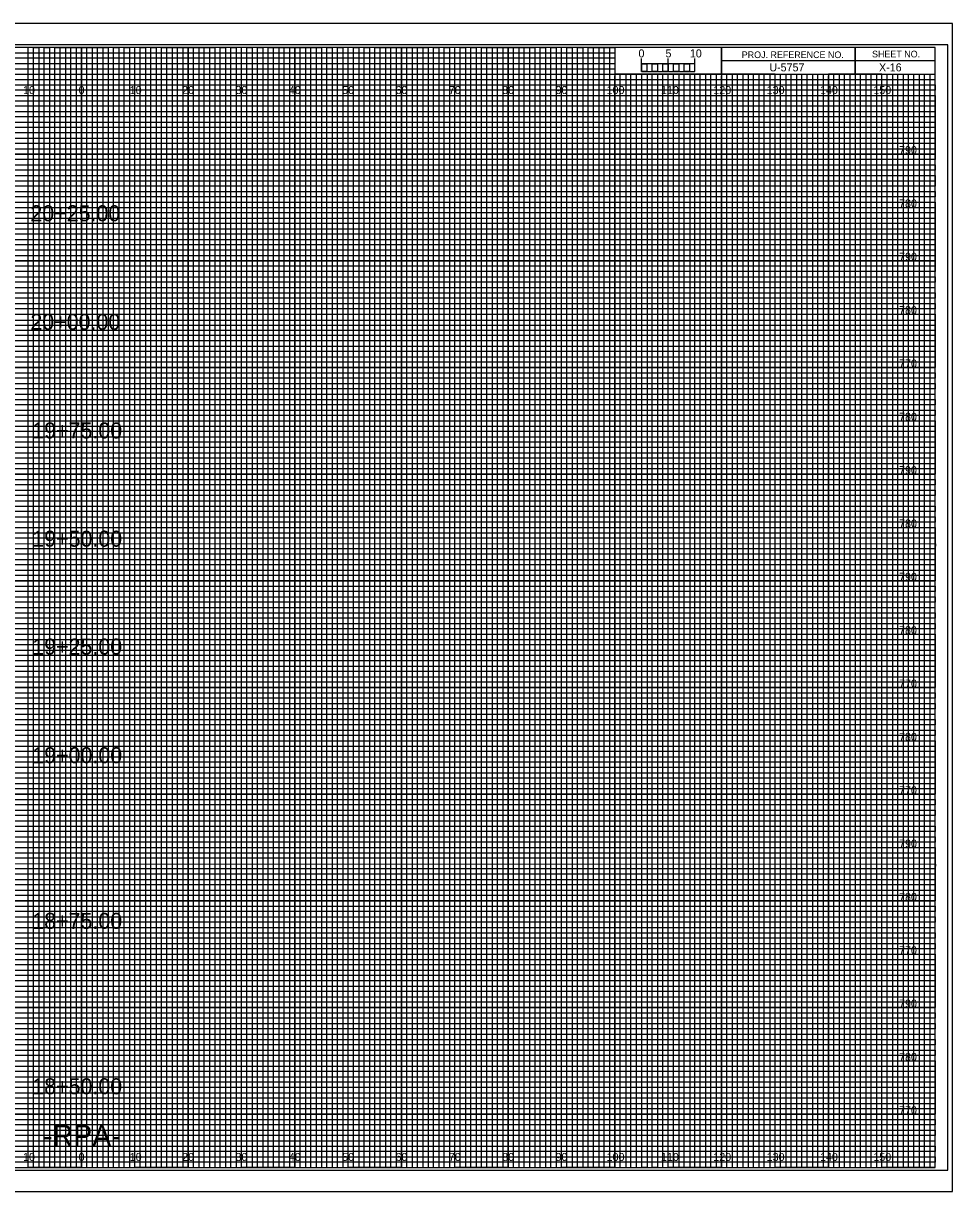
# Model space of a CAD drawing. Extents: x -13 to 323, y -5 to 215.
# Drawn here: x 149.1 to 323.3, y -4.5 to 214.5 of the extents above; entities that cross this region are included whole.
import ezdxf

# ---------------------------------------------------------------- set-up
doc = ezdxf.new("R2010")
doc.units = 0
for name, color, linetype in [('Exist Cross Section Cell', 7, 'Continuous'), ('Exist XS Center Line Elevation Label', 7, 'Continuous'), ('Exist XS Ground Line', 7, 'Continuous'), ('Prop CMT Pvmt Course 2', 7, 'Continuous'), ('Prop XS Alignment Label', 7, 'Continuous'), ('Prop XS Bar Scale Labels', 7, 'Continuous'), ('Prop XS DDE', 7, 'Continuous'), ('Prop XS DDE Elevations', 7, 'Continuous'), ('Prop XS Elevation Labels', 7, 'Continuous'), ('Prop XS Offset Labels', 7, 'Continuous'), ('Prop XS Project Number', 7, 'Continuous'), ('Prop XS Sheet Number', 7, 'Continuous'), ('Prop XS Side Slope Text', 7, 'Continuous'), ('Prop XS Station Labels', 7, 'Continuous'), ('Sheet Cutting Line CELL', 7, 'Continuous'), ('Sheet DOT Grid CELL', 7, 'Continuous'), ('Sheet Plot Border Outside CELL', 7, 'Continuous')]:
    doc.layers.add(name, color=color, linetype=linetype)

msp = doc.modelspace()

# ---------------------------------------------------------------- linework, layer by layer
at = {"layer": 'Exist Cross Section Cell'}
for p, q in [((150, 210), (140, 210)), ((150, 0), (150, 210)), ((170, 210), (160, 210)), ((160, 210), (160, 0)), ((170, 0), (170, 210)), ((190, 210), (180, 210)), ((180, 210), (180, 0)), ((190, 0), (190, 210)), ((210, 210), (200, 210)), ((200, 210), (200, 0)), ((210, 0), (210, 210)), ((230, 210), (220, 210)), ((220, 210), (220, 0)), ((230, 0), (230, 210)), ((250, 210), (240, 210)), ((240, 210), (240, 0)), ((250, 0), (250, 210)), ((260, 210), (260, 0)), ((270, 0), (270, 205)), ((290, 205), (280, 205)), ((280, 205), (280, 0)), ((290, 0), (290, 205)), ((310, 205), (300, 205)), ((300, 205), (300, 0)), ((310, 0), (310, 205)), ((160, 0), (150, 0)), ((180, 0), (170, 0)), ((200, 0), (190, 0)), ((220, 0), (210, 0)), ((240, 0), (230, 0)), ((260, 0), (250, 0)), ((280, 0), (270, 0)), ((300, 0), (290, 0)), ((320, 0), (310, 0)), ((320, 0), (320, 0))]:
    msp.add_line(p, q, dxfattribs=at)
for points in [[(0, 200), (320, 200), (320, 190), (0, 190)], [(0, 180), (320, 180), (320, 170), (0, 170)], [(0, 160), (320, 160), (320, 150), (0, 150)], [(0, 140), (320, 140), (320, 130), (0, 130)], [(0, 120), (320, 120), (320, 110), (0, 110)], [(0, 100), (320, 100), (320, 90), (0, 90)], [(0, 80), (320, 80), (320, 70), (0, 70)], [(0, 60), (320, 60), (320, 50), (0, 50)], [(0, 40), (320, 40), (320, 30), (0, 30)], [(0, 20), (320, 20), (320, 10), (0, 10)]]:
    msp.add_lwpolyline(points, dxfattribs=at)
at = {"layer": 'Exist XS Center Line Elevation Label'}
for p, q in [((0, 209), (260, 209)), ((260, 209), (260, 207.98)), ((260, 207.98), (0, 207.98)), ((0, 207), (260, 207)), ((260, 205.89), (0, 205.89)), ((260, 207), (260, 205.89)), ((0, 204), (320, 204))]:
    msp.add_line(p, q, dxfattribs=at)
for points in [[(0, 203), (270, 203), (320, 203), (320, 202), (0, 202)], [(0, 201), (320, 201), (320, 199), (0, 199)], [(0, 198), (320, 198), (320, 197), (0, 196.98)], [(0, 196), (320, 196), (320, 194), (0, 194)], [(0, 193), (320, 193), (320, 192), (0, 192)], [(0, 191), (320, 191), (320, 189), (0, 189)], [(0, 188), (320, 188), (320, 187), (0, 187)], [(0, 186), (320, 186), (320, 184), (0, 184)], [(0, 183), (320, 183), (320, 182), (0, 182)], [(0, 181), (320, 181), (320, 179), (0, 179)], [(0, 178), (320, 178), (320, 177), (0, 177)], [(0, 176), (320, 176), (320, 173.95), (320, 173), (320, 172), (0, 172)], [(0, 174), (320, 174), (320, 173), (0, 173)], [(0, 171), (320, 171), (320, 169), (0, 169.03)], [(0, 169.03), (320, 169), (320, 168), (0, 168)], [(0, 167), (320, 167), (320, 166), (0, 166)], [(0, 164), (320, 164), (320, 163), (0, 163)], [(0, 162), (320, 162), (320, 161), (0, 161)], [(-0.07, 158.89), (320, 158.89), (320, 157.88), (-0.07, 157.88)], [(0, 157), (320, 157), (320, 156), (0, 156)], [(0, 154), (320, 154), (320, 153), (0, 153)], [(0, 152), (320, 152), (320, 151), (0, 151)], [(0, 149), (320, 149), (320, 148), (0, 148)], [(0, 147), (320, 147), (320, 146), (0, 146)], [(0, 144), (320, 144), (320, 143), (0, 143)], [(0, 142), (320, 142), (320, 141), (0, 141)], [(0, 139), (320, 139), (319.99, 137.98), (0, 138)], [(0, 137), (320, 137), (320, 136), (0, 136)], [(0, 134), (320, 134), (320, 133), (0, 133)], [(0, 132), (320, 132), (320, 131), (0, 131)], [(0, 129), (320, 129), (320, 128), (0, 128)], [(0, 127), (320, 127), (320, 126), (0, 126)], [(0, 124), (320, 124), (320, 123), (0, 123)], [(0, 122), (320, 122), (320, 121), (0, 121)], [(0, 119), (320, 119), (320, 118), (0, 118)], [(0, 116.99), (320.07, 116.91), (320, 116), (0, 116)], [(0, 114), (320, 114), (320, 113), (0, 113)], [(0, 112), (320, 112), (320, 111), (0, 111)], [(0, 109), (320, 109), (320, 108), (0, 108)], [(0, 107), (320, 107), (320, 106), (0, 106)], [(0, 104), (320, 104), (320, 103), (0, 103)], [(0, 102), (320, 102), (320, 101), (0, 101)], [(0, 99), (320, 99), (320, 98), (0, 98)], [(0, 97), (320, 97), (320, 96), (0, 96)], [(0, 94), (320, 94), (320, 93), (0, 93)], [(0, 92), (320, 92), (320, 91), (0, 91)], [(0, 89), (320, 89), (320, 88), (0, 88)], [(0, 87), (320, 87), (320, 86), (0, 86)], [(0, 84), (320, 84), (320, 83), (0, 83)], [(0, 82), (320, 82), (320, 81), (0, 81)], [(0, 79), (320, 79), (319.99, 77.98), (0, 78)], [(0, 77), (320, 77), (320, 76), (0, 76)], [(0, 74), (320, 74), (320, 73), (0, 73)], [(0, 72), (320, 72), (320, 71), (0, 71)], [(0, 69), (320, 69), (320, 68), (0, 68)], [(0, 67), (320, 67), (320, 66), (0, 66)], [(0, 64), (320, 64), (320, 63), (0, 63)], [(0, 62), (320, 62), (320, 61), (0, 61)], [(0, 59), (320, 59), (320, 58), (0, 58)], [(0, 56.99), (320.07, 56.91), (320, 56), (0, 56)], [(0, 54), (320, 54), (320, 53), (0, 53)], [(0, 52), (320, 52), (320, 51), (0, 51)], [(0, 49), (320, 49), (320, 48), (0, 48)], [(0, 47), (320, 47), (320, 46), (0, 46)], [(0, 44), (320, 44), (320, 43), (0, 43)], [(0, 42), (320, 42), (320, 41), (0, 41)], [(0, 39), (320, 39), (320, 38), (0, 38)], [(0, 37), (320, 37), (320, 36), (0, 36)], [(0, 34), (320, 34), (320, 33), (0, 33)], [(0, 32), (320, 32), (320, 31), (0, 31)], [(0, 29), (320, 29), (320, 28), (0, 28)], [(0, 27), (320, 27), (320, 26), (0, 26)], [(0, 24), (320, 24), (320, 23), (0, 23)], [(0, 22), (320, 22), (320, 21), (0, 21)], [(0, 19), (320, 19), (320, 18), (0, 18)], [(0, 17), (320, 17), (320, 16), (0, 16)], [(0, 14), (320, 14), (320, 13), (0, 13)], [(0, 12), (320, 12), (320, 11), (0, 11)], [(0, 9), (320, 9), (320, 8), (0, 8)], [(0, 7), (320, 7), (320, 6), (0, 6)], [(0, 4), (320, 4), (320, 3), (0, 3)], [(0, 2), (320, 2), (320, 1), (0, 1)]]:
    msp.add_lwpolyline(points, dxfattribs=at)
at = {"layer": 'Exist XS Ground Line'}
for points in [[(145, 0), (155, 0), (155, 210), (165, 210), (165, 0), (175, 0), (175, 210), (185, 210), (185, 0), (195, 0), (195, 210), (205, 210), (205, 0), (215, 0), (215, 210), (225, 210), (225, 0), (235, 0), (235, 210), (245, 210), (245, 0), (255, 0), (255, 210), (259.93, 210), (260, 210), (260, 205), (264.99, 205), (264.99, 0), (275, 0), (275, 205), (285, 205), (285, 0), (295, 0), (295, 205), (305, 205), (305, 0), (315, 0), (315, 205)], [(0, 205), (275, 205)], [(0, 185), (320, 185), (320, 195), (0, 195)], [(0, 165), (320, 165), (320, 175), (0, 175)], [(0, 145), (320, 145), (320, 155), (0, 155)], [(0, 125), (320, 125), (320, 135), (0, 135)], [(0, 105), (320, 105), (320, 115), (0, 115)], [(0, 85), (320, 85), (320, 95), (0, 95)], [(0, 65), (320, 65), (320, 75), (0, 75)], [(0, 45), (320, 45), (320, 55), (0, 55)], [(0, 25), (320, 25), (320, 35), (0, 35)], [(0, 5), (320, 5), (320, 15), (0, 15)]]:
    msp.add_lwpolyline(points, dxfattribs=at)
at = {"layer": 'Prop CMT Pvmt Course 2'}
msp.add_lwpolyline([(-10.8, -0.5), (322.4, -0.5), (322.4, 210.5), (-10.8, 210.5)], close=True, dxfattribs=at)
at = {"layer": 'Prop XS DDE'}
for p, q in [((305, 210), (305, 205)), ((305, 205), (305, 210)), ((280, 207.5), (280, 205)), ((320, 207.49), (280, 207.49)), ((280, 205), (320, 205))]:
    msp.add_line(p, q, dxfattribs=at)
for points in [[(320, 210), (0, 210), (0, 0), (320, 0)], [(280, 210), (260, 210), (260, 205.03), (280, 205.03)], [(320, 210), (280, 210), (280, 205), (320, 205)]]:
    msp.add_lwpolyline(points, close=True, dxfattribs=at)
at = {"layer": 'Prop XS DDE Elevations'}
for p, q in [((267, 205), (266.01, 205)), ((266.01, 205), (266.01, 0)), ((267, 0), (267, 205)), ((269, 205), (268, 205)), ((268, 205), (268, 0)), ((269, 0), (269, 205)), ((266.01, 0), (265, 0)), ((268, 0), (267, 0))]:
    msp.add_line(p, q, dxfattribs=at)
for points in [[(150, 0), (151, 0), (151, 210), (152, 210), (152, 0)], [(152, 0), (153, 0), (153, 210), (154, 210), (154, 0)], [(155, 0), (156, 0), (156, 210), (157, 210), (157, 0)], [(157, 0), (158, 0), (158, 210), (159, 210), (159, 0)], [(160, 0), (161, 0), (161, 210), (162, 210), (162, 0)], [(162, 0), (163, 0), (163, 210), (164, 210), (164, 0)], [(165, 0), (166, 0), (166, 210), (167, 210), (167, 0)], [(167, 0), (168, 0), (168, 210), (169, 210), (169, 0)], [(170, 0), (171, 0), (171, 210), (172, 210), (172, 0)], [(172, 0), (173, 0), (173, 210), (174, 210), (174, 0)], [(175, 0), (176, 0), (176, 210), (177, 210), (177, 0)], [(177, 0), (178, 0), (178, 210), (179, 210), (179, 0)], [(180, 0), (181, 0), (181, 210), (182, 210), (182, 0)], [(182, 0), (183, 0), (183, 210), (184, 210), (184, 0)], [(185, 0), (186, 0), (186, 210), (187, 210), (187, 0)], [(187, 0), (188, 0), (188, 210), (189, 210), (189, 0)], [(190, 0), (191, 0), (191, 210), (192, 210), (192, 0)], [(192, 0), (193, 0), (193, 210), (194, 210), (194, 0)], [(195, 0), (196, 0), (196, 210), (197, 210), (197, 0)], [(197, 0), (198, 0), (198, 210), (199, 210), (199, 0)], [(200, 0), (201, 0), (201, 210), (202, 210), (202, 0)], [(202, 0), (203, 0), (203, 210), (204, 210), (204, 0)], [(205, 0), (206, 0), (206, 210), (207, 210), (207, 0)], [(207, 0), (208, 0), (208, 210), (209, 210), (209, 0)], [(210, 0), (211, 0), (211, 210), (212, 210), (212, 0)], [(212, 0), (213, 0), (213, 210), (214, 210), (214, 0)], [(215, 0), (216, 0), (216, 210), (217, 210), (217, 0)], [(217, 0), (218, 0), (218, 210), (219, 210), (219, 0)], [(220, 0), (221, 0), (221, 210), (222, 210), (222, 0)], [(222, 0), (223, 0), (223, 210), (224, 210), (224, 0)], [(225, 0), (226, 0), (226, 210), (227, 210), (227, 0)], [(227, 0), (228, 0), (228, 210), (229, 210), (229, 0)], [(230, 0), (231, 0), (231, 210), (232, 210), (232, 0)], [(232, 0), (233, 0), (233, 210), (234, 210), (234, 0)], [(235, 0), (236, 0), (236, 210), (237, 210), (237, 0)], [(237, 0), (238, 0), (238, 210), (239, 210), (239, 0)], [(240, 0), (241, 0), (241, 210), (242, 210), (242, 0)], [(242, 0), (243, 0), (243, 210), (244, 210), (244, 0)], [(245, 0), (246, 0), (246, 210), (247, 210), (247, 0)], [(247, 0), (248, 0), (248, 210), (249, 210), (249, 0)], [(250, 0), (251, 0), (251, 210), (252, 210), (252, 0)], [(252, 0), (253, 0), (253, 210), (254, 210), (254, 0)], [(255, 0), (256, 0), (256, 210), (257, 210), (257, 0)], [(257, 0), (258, 0), (258, 210), (259, 210), (259, 0)], [(260, 0), (261, 0), (261, 205), (262.02, 205), (262.02, 0)], [(262, 0), (263, 0), (263, 205), (263.99, 205), (263.99, 0)], [(270, 0), (270.98, 0), (270.98, 205), (272, 205), (272, 0)], [(272, 0), (273, 0), (273, 205), (274.05, 205), (274.05, 0)], [(275, 0), (276, 0), (276, 205), (277, 205), (277, 0)], [(277, 0), (278, 0), (278, 205), (279, 205), (279, 0)], [(280, 0), (281, 0), (281, 205), (282, 205), (282, 0)], [(282, 0), (283, 0), (283, 205), (284, 205), (284, 0)], [(285, 0), (286, 0), (286, 205), (287, 205), (287, 0)], [(287, 0), (288, 0), (288, 205), (289, 205), (289, 0)], [(290, 0), (291, 0), (291, 205), (292, 205), (292, 0)], [(292, 0), (293, 0), (293, 205), (294, 205), (294, 0)], [(295, 0), (296, 0), (296, 205), (297, 205), (297, 0)], [(297, 0), (298, 0), (298, 205), (299, 205), (299, 0)], [(300, 0), (301, 0), (301, 205), (302, 205), (302, 0)], [(302, 0), (303, 0), (303, 205), (304, 205), (304, 0)], [(305, 0), (306, 0), (306, 205), (307, 205), (307, 0)], [(307, 0), (308, 0), (308, 205), (309, 205), (309, 0)], [(310, 0), (311, 0), (311, 205), (312, 205), (312, 0)], [(312, 0), (313, 0), (313, 205), (314, 205), (314, 0)], [(315, 0), (316, 0), (316, 205), (317, 205), (317, 0)], [(317, 0), (318, 0), (318, 205), (319, 205), (319, 0)]]:
    msp.add_lwpolyline(points, dxfattribs=at)
at = {"layer": 'Prop XS Side Slope Text'}
for p, q in [((265, 205.49), (265, 207.9)), ((265, 206.9), (265, 207.9)), ((270, 205.49), (270, 207.9)), ((275, 205.49), (275, 207.9)), ((275, 206.9), (275, 207.9))]:
    msp.add_line(p, q, dxfattribs=at)
for points in [[(275, 206.9), (265, 206.9), (265, 205.49), (275, 205.49)], [(265, 206.9), (266, 206.9), (266, 205.49), (265, 205.49)], [(267, 206.9), (268, 206.9), (268, 205.49), (267, 205.49)], [(269, 206.9), (270, 206.9), (270, 205.49), (269, 205.49)], [(271, 206.9), (272, 206.9), (272, 205.49), (271, 205.49)], [(273, 206.9), (274, 206.9), (274, 205.49), (273, 205.49)]]:
    msp.add_lwpolyline(points, close=True, dxfattribs=at)
at = {"layer": 'Sheet Cutting Line CELL'}
for p, q in [((323.3, 214.5), (-13.4, 214.5)), ((-13.4, -4.5), (323.3, -4.5))]:
    msp.add_line(p, q, dxfattribs=at)
at = {"layer": 'Sheet DOT Grid CELL'}
for p, q in [((150, 0), (150, 210)), ((160, 0), (160, 210)), ((170, 0), (170, 210)), ((180, 0), (180, 210)), ((190, 0), (190, 210)), ((200, 0), (200, 210)), ((210, 0), (210, 210)), ((220, 0), (220, 210)), ((230, 0), (230, 210)), ((240, 0), (240, 210)), ((250, 0), (250, 210)), ((260, 0), (260, 204.69)), ((270, 0), (270, 204.69)), ((280, 0), (280, 204.69)), ((290, 0), (290, 204.69)), ((300, 0), (300, 204.69)), ((310, 0), (310, 204.69)), ((0, 200), (320, 200)), ((0, 190), (320, 190)), ((0, 180), (320, 180)), ((0, 170), (320, 170)), ((0, 160), (320, 160)), ((0, 150), (320, 150)), ((0, 140), (320, 140)), ((0, 130), (320, 130)), ((0, 120), (320, 120)), ((0, 110), (320, 110)), ((0, 100), (320, 100)), ((0, 90), (320, 90)), ((0, 80), (320, 80)), ((0, 70), (320, 70)), ((0, 60), (320, 60)), ((0, 50), (320, 50)), ((0, 40), (320, 40)), ((0, 30), (320, 30)), ((0, 20), (320, 20)), ((0, 10), (320, 10))]:
    msp.add_line(p, q, dxfattribs=at)
at = {"layer": 'Sheet Plot Border Outside CELL'}
msp.add_lwpolyline([(-13.4, -4.5), (323.3, -4.5), (323.3, 214.5), (-13.4, 214.5)], close=True, dxfattribs=at)

# ---------------------------------------------------------------- texts
at = {"layer": 'Prop XS Alignment Label'}
msp.add_text('-RPA-', height=4, dxfattribs=at).set_placement((152.79, 4))
at = {"layer": 'Prop XS Bar Scale Labels'}
for s, p in [('5', (269.47, 208.12)), ('10', (274.04, 208.12))]:
    msp.add_text(s, height=1.5, dxfattribs=at).set_placement(p)
at = {"layer": 'Prop XS DDE'}
for s, p in [('PROJ. REFERENCE NO.', (283.77, 207.99)), ('SHEET NO.', (308.19, 208.12))]:
    msp.add_text(s, height=1.25, dxfattribs=at).set_placement(p)
at = {"layer": 'Prop XS Elevation Labels'}
for s, p in [('790', (313.26, 190)), ('780', (313.26, 180)), ('790', (313.26, 170)), ('780', (313.26, 160)), ('770', (313.26, 150)), ('780', (313.26, 140)), ('790', (313.26, 130)), ('780', (313.26, 120)), ('790', (313.26, 110)), ('780', (313.26, 100)), ('770', (313.26, 90)), ('780', (313.26, 80)), ('770', (313.26, 70)), ('790', (313.26, 60)), ('780', (313.26, 50)), ('770', (313.26, 40)), ('790', (313.26, 30)), ('780', (313.26, 20)), ('770', (313.26, 10))]:
    msp.add_text(s, height=1.5, dxfattribs=at).set_placement(p)
at = {"layer": 'Prop XS Offset Labels'}
for s, p in [('10', (149.04, 201.25)), ('0', (159.45, 201.25)), ('0', (159.45, 201.25)), ('10', (169.04, 201.25)), ('20', (178.86, 201.25)), ('30', (188.86, 201.25)), ('40', (198.86, 201.25)), ('50', (208.86, 201.25)), ('60', (218.86, 201.25)), ('70', (228.86, 201.25)), ('80', (238.86, 201.25)), ('90', (248.86, 201.25)), ('100', (258.44, 201.25)), ('110', (268.62, 201.25)), ('120', (278.44, 201.25)), ('130', (288.44, 201.25)), ('140', (298.44, 201.25)), ('150', (308.44, 201.25)), ('10', (149.04, 1.25)), ('0', (159.45, 1.25)), ('0', (159.45, 1.25)), ('10', (169.04, 1.25)), ('20', (178.86, 1.25)), ('30', (188.86, 1.25)), ('40', (198.86, 1.25)), ('50', (208.86, 1.25)), ('60', (218.86, 1.25)), ('70', (228.86, 1.25)), ('80', (238.86, 1.25)), ('90', (248.86, 1.25)), ('100', (258.44, 1.25)), ('110', (268.62, 1.25)), ('120', (278.44, 1.25)), ('130', (288.44, 1.25)), ('140', (298.44, 1.25)), ('150', (308.44, 1.25))]:
    msp.add_text(s, height=1.5, dxfattribs=at).set_placement(p)
at = {"layer": 'Prop XS Project Number'}
msp.add_text('U-5757', height=1.5, dxfattribs=at).set_placement((288.94, 205.5))
at = {"layer": 'Prop XS Sheet Number'}
msp.add_text('X-16', height=1.5, dxfattribs=at).set_placement((309.5, 205.5))
at = {"layer": 'Prop XS Side Slope Text'}
msp.add_text('0', height=1.5, dxfattribs=at).set_placement((264.41, 208.12))
at = {"layer": 'Prop XS Station Labels'}
for s, p in [('20+25.00', (150.41, 177.4)), ('20+00.00', (150.41, 157.05)), ('19+75.00', (150.77, 136.69)), ('19+50.00', (150.77, 116.4)), ('19+25.00', (150.77, 96.17)), ('19+00.00', (150.77, 75.81)), ('18+75.00', (150.77, 44.76)), ('18+50.00', (150.77, 13.75))]:
    msp.add_text(s, height=3, dxfattribs=at).set_placement(p)

doc.saveas('drawing.dxf')
